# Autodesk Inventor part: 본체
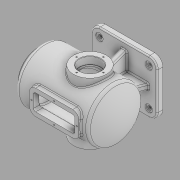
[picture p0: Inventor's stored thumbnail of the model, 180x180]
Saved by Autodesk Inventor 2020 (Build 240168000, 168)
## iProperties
Created: 2021-11
Part Number: 본체
Material: 일반
Document SubType Name: Modeling
Designer: Administrator
Density: 1 g/cm^3
Appearance: 기본값
Author: Administrator
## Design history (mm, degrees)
sketch "스케치1"
  geometry: L1 (-80, 65)-(80, 65); L2 (80, 65)-(80, -65); L3 (80, -65)-(-80, -65); L4 (-80, -65)-(-80, 65); L5 (-80, 65)-(80, -65); L6 (80, 65)-(-80, -65); 1 further point
  constraints: 12 end point, 2 midpoint, 2 parallel, 1 horizontal, 1 perpendicular
  dimensions: "d0" = 160 distance of L1.start L1.end; "d1" = 130 distance of L3.end L1.start
extrude "돌출1" new body sketch "스케치1" distance "d2" = 14; taper "d3" = 0 deg
sketch "스케치2"
  geometry: L1 (110, 114)-(-120.721, 114); L2 (80, 0)-(-80, 0) reference; L3 (110, 114)-(110, 161.5); L4 (110, 161.5)-(100, 161.5); L5 (100, 161.5)-(100, 179); L6 (110, 114)-(-100, 114); L7 (80, 0)-(80, 14) reference; L8 (110, 146.5)-(85, 146.5); L9 (85, 146.5)-(85, 169); L10 (85, 169)-(-71.239, 169); L11 (100, 179)-(-75.993, 179); A1 r 100 centre (0, 114) between (-75.993, 179) and (-75.993, 49); A2 r 90 centre (0, 114) between (-71.239, 169) and (-68.394, 55.5); 3 further points
  constraints: 18 end point, 5 point on circle, 4 perpendicular, 3 horizontal, 2 centre point, 1 point on line, 1 vertical, 1 vertical alignment
  dimensions: "d4" = 114 distance between parallel lines of L1 L2; "d6" = 95 diameter of L4 L1; "d8" = 100 radius of A1; "d9" = 130 distance of A1.end L11.end; "d10" = 210 distance from line of L6.end L3; "d11" = 10 distance of L3.end L4.end; "d12" = 30 distance between parallel lines of L7 L3; "d15" = 65 diameter of L8 L1; "d17" = 10 radial gap between concentric circles of A1 A2; "d18" = 130 diameter of L11 L1; "d19" = 10 distance between parallel lines of L10 L11; "d20" = 25 distance between parallel lines of L9 L3
revolve "회전1" sketch "스케치2" stored, may be unused: angle "d21" = 90 deg
sketch "스케치3"
  geometry: L1 (-7, 7)-(7, 7); L2 (7, 7)-(7, -7); L3 (7, -7)-(-7, -7); L4 (-7, -7)-(-7, 7); L5 (-7, 7)-(7, -7); L6 (7, 7)-(-7, -7); 1 further point
  constraints: 12 end point, 2 midpoint, 2 parallel, 1 horizontal, 1 perpendicular
  dimensions: "d22" = 14 distance of L1.start L1.end; "d23" = 14 distance of L1.end L2.end
extrude "돌출2" join sketch "스케치3" stored distance "d24" = 14; taper "d25" = 0 deg
sketch "스케치4"
  geometry: L1 (60, 14)-(48.273, 46.219); L2 (80, 14)-(-80, 14) reference; 1 further point
  constraints: 2 end point, 1 point on line
  dimensions: "d26" = 60 horizontal distance of L1.start point (0, 0); "d27" = 110 deg angle of L2 L1
feature "리브1" sketch "스케치4" dims "d28" = 1, "d29" = 14, "d30" = 0, "d31" = 0, "d32" = 1, "d33" = 1
sketch "스케치5"
  geometry: L1 (-65, 14)-(65, 14) reference; L2 (-50, 14)-(-39.425, 43.055); 1 further point
  constraints: 2 end point, 1 point on line
  dimensions: "d34" = 50 horizontal distance of point (0, 0) L2.start; "d35" = 110 deg angle of L1 L2
feature "리브2" sketch "스케치5" dims "d36" = 1, "d37" = 14, "d38" = 0, "d39" = 0, "d40" = 1, "d41" = 1
node "작업 평면1"
sketch "스케치6"
  geometry: L1 (-110, 161.5)-(-110, 66.5) reference; C1 r 40 at (17, 114); 1 further point
  constraints: 1 centre point
  dimensions: "d43" = 114 vertical distance of C1.centre point (0, 0); "d44" = 80 diameter of C1; "d45" = 127 distance from line of C1.centre L1
extrude "돌출3" join sketch "스케치6" stored distance "d46" = 14; taper "d47" = 0 deg
sketch "스케치7"
  geometry: C1 r 40 at (0, 0) reference; 2 further points
  constraints: 1 coincident
hole "구멍1" sketch "스케치7" at (0, 0) diameter "d48" = 42; stored, may be unused: countersink angle "d52" = 82 deg, drill point angle "d54" = 0 deg; dims "d49" = 6, "d50" = 52, "d51" = 18, "d53" = 8
node "작업 평면2"
sketch "스케치8"
  geometry: L1 (-60, 30)-(60, 30); L2 (60, 30)-(60, -30); L3 (60, -30)-(-60, -30); L4 (-60, -30)-(-60, 30); L5 (-110, 47.5)-(-110, -47.5) reference; 2 further points
  constraints: 8 end point, 2 parallel, 1 horizontal, 1 horizontal alignment, 1 midpoint, 1 perpendicular
  dimensions: "d56" = 50 distance between parallel lines of L4 L5; "d57" = 120 distance of L1.start L1.end; "d58" = 60 distance between parallel lines of L3 L1
extrude "돌출4" join sketch "스케치8" stored distance "d59" = 14; taper "d60" = 0 deg
sketch "스케치9"
  geometry: L1 (60, 30)-(-60, 30) reference; L2 (60, -30)-(60, 30) reference; L3 (60, 30)-(-60, 30) reference; L4 (-60, 30)-(-60, -30) reference; L5 (-60, -30)-(60, -30) reference; L6 (50, 20)-(50, -20); L7 (50, -20)-(-50, -20); L8 (-50, -20)-(-50, 20); L9 (-50, 20)-(50, 20); 1 further point
  constraints: 8 end point, 3 other
  dimensions: "d61" = 10 distance between parallel lines of L2 L6
extrude "돌출5" cut sketch "스케치9" stored distance "d62" = 10; taper "d63" = 0 deg
fillet "모깎기1" dims "d64" = 15, "d65" = 5
sketch "스케치10"
  geometry: L1 (55, 0)-(-55, 0); L2 (0, 25)-(0, -25); L3 (60, -15)-(60, 15) reference; 2 further points
  constraints: 4 end point, 2 midpoint, 1 coincident, 1 horizontal, 1 vertical
  dimensions: "d66" = 50 distance of L2.start L2.end; "d67" = 110 distance of L1.start L1.end; "d68" = 5 distance from line of L1.start L3
hole "구멍2" sketch "스케치10" at (0, -25), (55, 0), (0, 25), (-55, 0) diameter "d69" = 3.242; stored, may be unused: countersink angle "d73" = 90 deg, drill point angle "d75" = 118 deg; dims "d70" = 9, "d71" = 52, "d72" = 18, "d74" = 11
sketch "스케치11" dims "d76" = 65
  geometry: L1 (0, 0)-(0, 32.5); C1 r 26 at (0, 0) reference; C2 r 40 at (0, 0) reference; 2 further points
  constraints: 2 coincident, 2 end point, 1 vertical, 1 vertical alignment, 2 other
hole "구멍3" sketch "스케치11" at (0, 32.5) diameter "d77" = 3.242; stored, may be unused: countersink angle "d81" = 90 deg, drill point angle "d83" = 118 deg; dims "d78" = 11, "d79" = 52, "d80" = 18, "d82" = 13
sketch "스케치12" dims "d87" = 80
  geometry: L1 (0, 0)-(40, 0); C1 r 47.5 at (0, 0) reference; 2 further points
  constraints: 2 coincident, 2 end point, 1 horizontal, 1 horizontal alignment, 2 other
hole "구멍4" sketch "스케치12" at (40, 0) diameter "d88" = 3.242; stored, may be unused: countersink angle "d92" = 90 deg, drill point angle "d94" = 118 deg; dims "d89" = 11, "d90" = 52, "d91" = 18, "d93" = 13
fillet "모깎기2" dims "d98" = 20
sketch "스케치13"
  geometry: A1 r 20 centre (-60, 45) between (-60, 65) and (-80, 45) reference; A2 r 20 centre (-60, -45) between (-80, -45) and (-60, -65) reference; A3 r 20 centre (60, -45) between (60, -65) and (80, -45) reference; A4 r 20 centre (60, 45) between (80, 45) and (60, 65) reference; 5 further points
  constraints: 4 coincident
hole "구멍5" sketch "스케치13" at (-60, 45), (-60, -45), (60, -45), (60, 45) diameter "d99" = 9; stored, may be unused: countersink angle "d103" = 90 deg, drill point angle "d105" = 0 deg; dims "d100" = 11, "d101" = 18, "d102" = 2, "d104" = 13
fillet "모깎기3" dims "d106" = 10
fillet "모깎기4" dims "d107" = 0.3
chamfer "모따기1" distance "d108" = 1; stored, may be unused: second distance "d109" = 2, angle "d110" = 45 deg
fillet "모깎기5" dims "d111" = 3
fillet "모깎기6" dims "d112" = 3
fillet "모깎기7" dims "d113" = 3
fillet "모깎기8" dims "d114" = 3
fillet "모깎기9" dims "d115" = 3
sketch "스케치14"
  geometry: L1 (39.261, 8.002)-(80.739, 8.002); L2 (80.739, 8.002)-(80.739, 1.998); L3 (80.739, 1.998)-(39.261, 1.998); L4 (39.261, 1.998)-(39.261, 8.002); L5 (39.261, 8.002)-(80.739, 1.998); L6 (0, 0)-(120, 0) reference; 3 further points
  constraints: 2 end point, 2 midpoint, 1 vertical alignment, 2 other
  dimensions: "d116" = 5 distance of point (60, 0) point (60, 5)
feature "엠보싱1" sketch "스케치14" dims "d117" = 0.5, "d118" = 0
node "솔리드1"
mirror "미러1"
mirror "미러2"
mirror "미러3"
mirror "미러4"
pattern_circular "원형 패턴1" dims angle "d85" = 360 deg
mirror "미러5"
pattern_circular "원형 패턴2" dims angle "d96" = 360 deg
node "투영된 루프1"
node "투영된 루프2"
feature "A9D066F2-1C7D-4E18-AEED-F7BC21143FA4" dims "d69" = 3.242, "d70" = 9, "d71" = 52, "d72" = 18, "d73" = 90 deg, "d74" = 11, "d75" = 118 deg
other parameters: "d42" = -75, "d55" = 184
